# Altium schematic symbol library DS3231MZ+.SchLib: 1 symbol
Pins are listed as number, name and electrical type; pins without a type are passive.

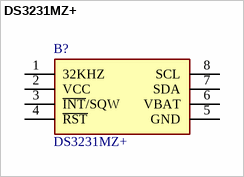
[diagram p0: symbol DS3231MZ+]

## DS3231MZ+
designator B?
Real Time Clock 5+/-ppm RTC; Manufacturer_Name: Analog Devices; Geometry.Height: 1.75mm
footprint SOIC127P600X175-8N
pins: 1 32KHZ, 2 VCC, 3 ~{INT}/SQW, 4 ~{RST}, 5 GND, 6 VBAT, 7 SDA, 8 SCL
